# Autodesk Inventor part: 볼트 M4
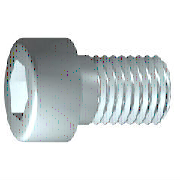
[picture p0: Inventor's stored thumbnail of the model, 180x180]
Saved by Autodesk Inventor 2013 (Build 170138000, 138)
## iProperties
IsCustomPart: 1
Created: 2012-02
Part Number: 볼트 M4
Material: 스테인리스강
Description: 6각 소켓 머리 캡 나사
Document SubType Name: Modeling
Standard: ISO 4762
Designer: mduedu
Standard Revision: Fourth edition 2004-03-01
Standards Organization: ISO
Language: ko-KR
Size Designation: M4 x 10
Categories: <MemberInstance><Categories><Category DisplayName="조임쇠" InternalName="e4da775c-781d-43d5-af7c-5136215cf5a6" Mnemonic="FSTN"><Category DisplayName="볼트" InternalN
Density: 7.75 g/cm^3
Author: mduedu
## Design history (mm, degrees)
sketch "스케치1"
  geometry: L1 (-1, 0)-(10, 0); L2 (10, 0)-(10, 2); L3 (10, 2)-(1.75, 2); L4 (1.75, 2)-(1.32, 2); L5 (1.32, 2)-(0, 2); L6 (0, 2)-(0, 3.5); L7 (0, 3.5)-(-4, 3.5); L8 (-4, 3.5)-(-4, 1.732); L9 (-4, 1.732)-(-2, 1.732); L10 (-2, 1.732)-(-1, 0); L11 (-6.8, 0)-(12.8, 0) reference; L12 (0, -0.7)-(0, 4.2) reference; L13 (1.75, 2)-(0, 2)
  constraints: 22 end point, 6 parallel, 2 collinear, 2 perpendicular, 1 horizontal, 1 point on line
  dimensions: "d1" = 8.25 distance from line of L3.end L2 (= GEL); "d2" = 0.42952 distance of L4.end L3.end (computed from GAL); "d3" = 4 distance between parallel lines of L8 L6 (= KOH); "d4" = 2 distance of L8.end L9.end (= INTI); "d5" = 60 deg angle of L10 L1; "d6" = 4 diameter of L3 L1 (= GD); "d7" = 4 diameter of L5 L1 (= BDM); "d8" = 3.4641 diameter of L9 L1 (= 1.1547 x SW); "d9" = 7 diameter of L7 L1 (= KOD); "d26" = 10 distance between parallel lines of L12 L2 (= NLG)
revolve "본체" sketch "스케치1" stored, may be unused: angle "d10" = 90 deg
sketch "스케치2"
  geometry: L1 (0, -4.9)-(0, 4.9) reference; L2 (-4.9, 0)-(4.9, 0) reference; L3 (1.732, 0)-(0.866, -1.5); L4 (0.866, -1.5)-(-0.866, -1.5); L5 (-0.866, -1.5)-(-1.732, 0); L6 (-1.732, 0)-(-0.866, 1.5); L7 (-0.866, 1.5)-(0.866, 1.5); L8 (0.866, 1.5)-(1.732, 0); 2 further points
  constraints: 12 end point, 1 coincident, 1 horizontal alignment, 1 point on line, 12 other
extrude "슬롯" join sketch "스케치2" stored distance "d11" = 10; taper "d12" = 0 deg
workplane "Work Plane1"
body "Solid1"
fillet "모깎기1" dims "d17" = 0.4 (= RR)
feature "스레드" dims "d13" = 8.25 (= GEL), "d14" = 0
chamfer "모따기1" distance "d15" = 0.42941 (= -0.5 x SPD + 0.5 x GD); stored, may be unused: second distance "d16" = 0.42941 (= GUL), angle "d27" = 45 deg
other parameters: "GD" = 4 [user parameter; used in 2 equation terms], "NLG" = 10 [user parameter; used in 1 equation term], "GEL" = 8.25 [user parameter; used in 2 equation terms], "KOD" = 7 [user parameter; used in 1 equation term], "KOH" = 4 [user parameter; used in 1 equation term], "INTI" = 2 [user parameter; used in 1 equation term], "GAL" = 0.42941 (= 0.61345 x PTC) [user parameter; used in 1 equation term], "GUL" = 0.42941 (= 0.61345 x PTC) [user parameter; used in 1 equation term], "BDM" = 4 (= NND) [user parameter; used in 1 equation term], "SW" = 3 [user parameter; used in 2 equation terms], "RR" = 0.4 [user parameter; used in 1 equation term], "SPD" = 3.14117 (= NND - 1.2269 x PTC) [user parameter; used in 1 equation term], "d19" = 0, "d28" = 0, "d29" = 0, "R" = 0.1 [user parameter], "TOA" = 30 deg [user parameter], "GD1" = 3.14117 (= THREADDIA - 1.2269 x PTC) [user parameter], "THREADDIA" = 4 [user parameter; used in 1 equation term], "FAWI" = 45 deg [user parameter], "TPU" = 14.28571 (computed from PTC) [user parameter], "PTC" = 0.7 [user parameter; used in 5 equation terms], "NND" = 4 [user parameter; used in 2 equation terms], "E0" = 3.465 (= 1.155 x SW) [user parameter]
